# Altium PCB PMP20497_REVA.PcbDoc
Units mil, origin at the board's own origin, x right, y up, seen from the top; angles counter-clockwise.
Board outline 4000 x 2000 mil, 2 copper layers (Top Layer, Bottom Layer), stack 62 mil thick; 81 components, 31 nets, 187 pads, 65 vias.
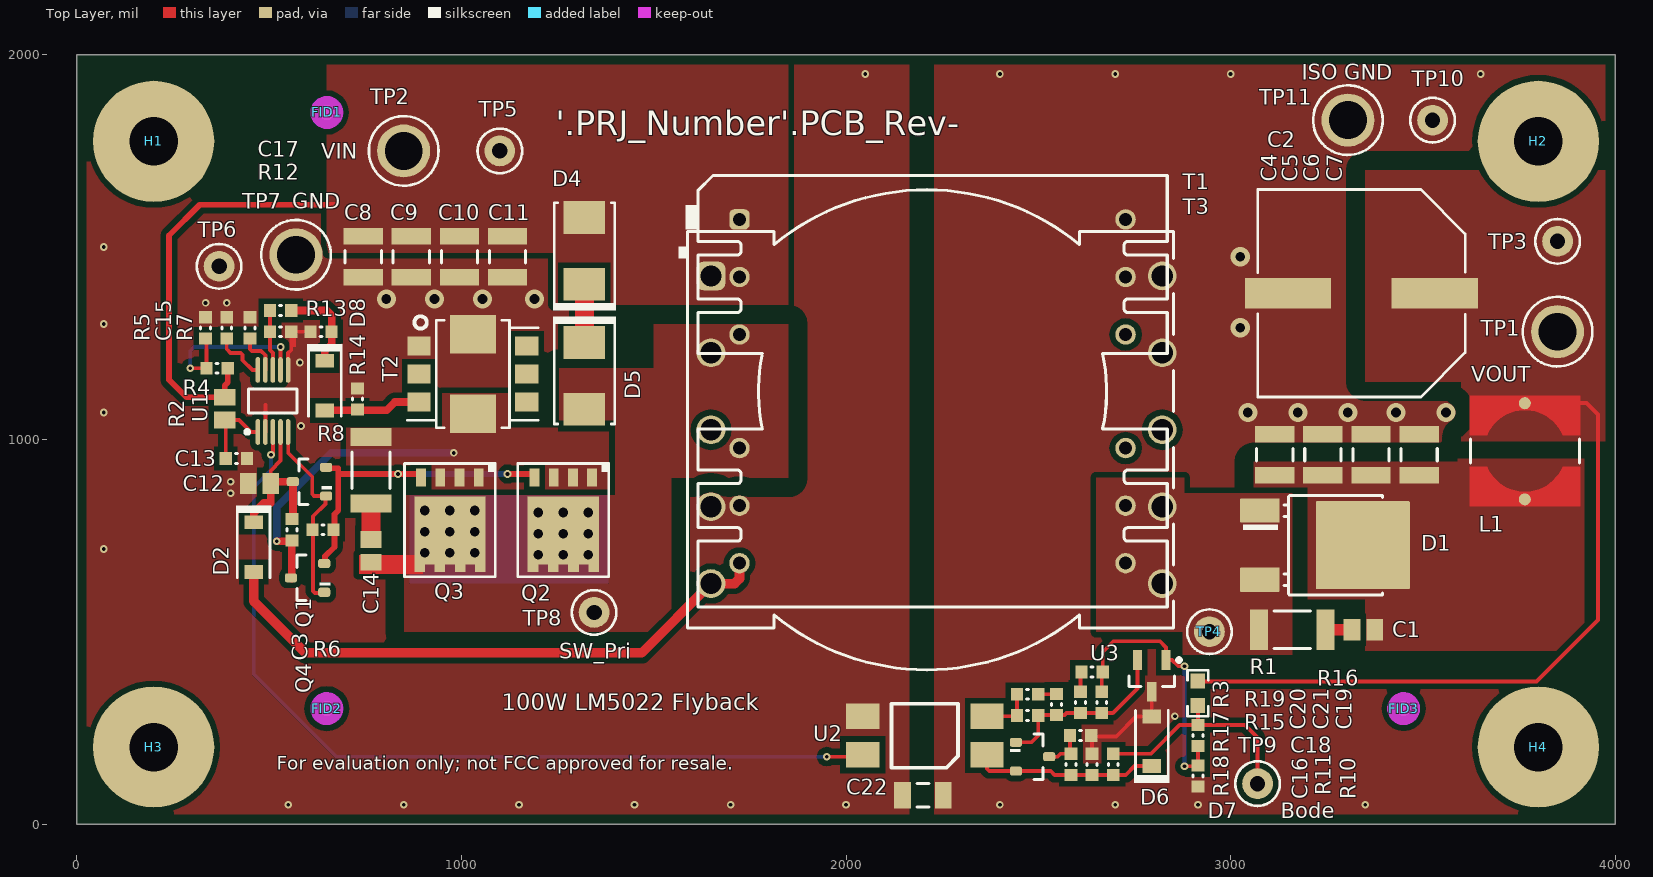
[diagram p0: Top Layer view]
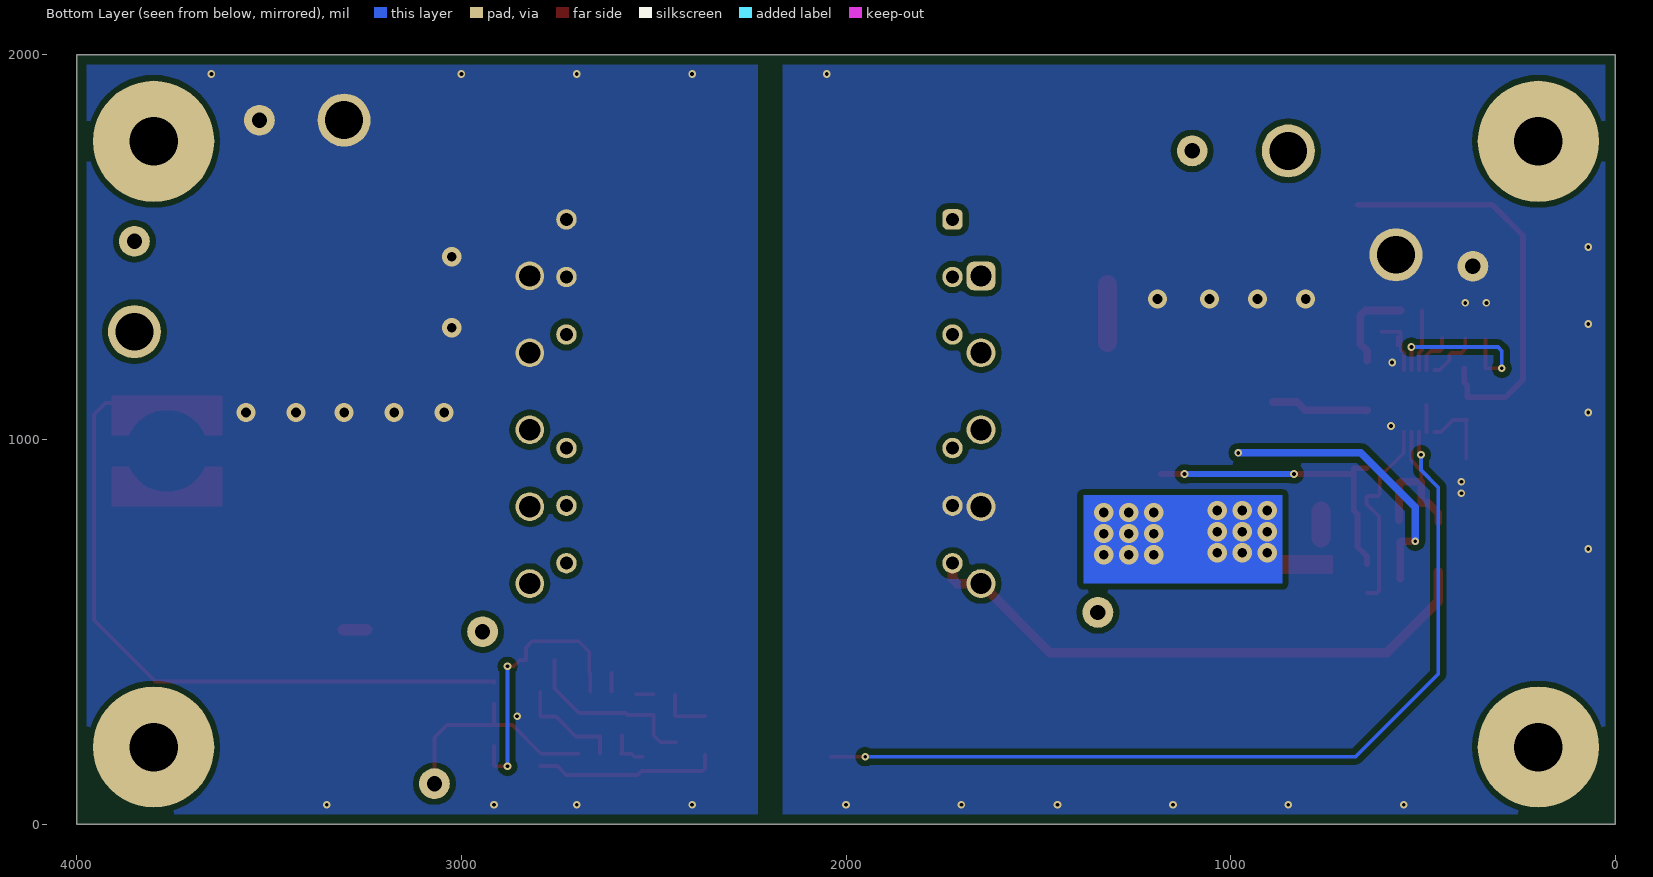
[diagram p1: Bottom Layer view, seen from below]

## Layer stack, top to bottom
Top Solder: solder mask 0.4, Solder Resist, Dk 3.5
Top Layer: signal copper 1.4
Dielectric1: core 59.2, FR-4, Dk 4.8
Bottom Layer: signal copper 1.4
Bottom Solder: solder mask 0.4, Solder Resist, Dk 3.5

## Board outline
0,0 4000,0 4000,2000 0,2000

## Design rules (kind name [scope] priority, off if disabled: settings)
AcuteAngle [All] p1: minimum=4.50000000000000E+0001 checktracksonly=FALSE
AssemblyTestPointUsage [All] p1: valid=2
BoardOutlineClearance BoardOutlineClearance_MountingHoles [OnCopper and InComponentClass('Mounting Holes')] p1: gap=40
BoardOutlineClearance BoardOutlineClearance_Poly [OnCopper and IsPoly] p2: gap=25
BoardOutlineClearance [OnCopper and Not InComponentClass('Logo') and not InComponentClass('FiducialMark') and not InRegion(1000,500,4000,800) and not InPoly] p3: gap=40
Clearance Clearance_NETC1 [(InPolygon AND InNet('netc1_1')) vs InNet('ISO GND')] p1: gap=50
Clearance Clearance_Vout_ISOGND [(InPolygon AND InNet('VOUT')) vs InNet('ISO GND')] p2: gap=50
Clearance Clearance_SWP_GND [(InPolygon AND InNet('SWP')) vs InNet('GND')] p3: gap=50
Clearance Clearance_Keepouts [((IsTrack Or IsArc) And Not InPoly) And IsFree and IsKeepOut vs ((IsTrack Or IsArc) And Not InPoly) And IsFree and IsKeepOut] p4: gap=0
Clearance Clearance_Poly [InPolygon] p5: gap=15
Clearance [All] p6: gap=7.87
ComponentClearance ComponentClearance_Inductor [(HasFootprint('Pulse_PA4621NL') OR HasFootprint ('Pulse_PA4826NL')) vs (HasFootprint('Pulse_PA4621NL') OR HasFootprint ('Pulse_PA4826NL'))] p1: gap=0 collisioncheckmode=3 verticalgap=0 showdistances=FALSE
ComponentClearance ComponentClearance_MountingHoles_FiducialMarks [InComponentClass('Mounting Holes') vs InComponentClass('FiducialMark')] p2: gap=50 collisioncheckmode=3 verticalgap=10 showdistances=FALSE
ComponentClearance ComponentClearance_Shunt [InComponentClass('Header') vs InComponentClass('Shunt')] p3: gap=0 collisioncheckmode=3 verticalgap=0 showdistances=FALSE
ComponentClearance ComponentClearance_Logo [InComponentClass('Logo')] p4: gap=50 collisioncheckmode=3 verticalgap=10 showdistances=FALSE
ComponentClearance ComponentClearance_ScrewToNut [(HasFootprint('NY PMS 440 0025 PH')) vs (HasFootprint('Keystone_1902C'))] p5: gap=5 collisioncheckmode=3 verticalgap=10 showdistances=FALSE
ComponentClearance ComponentClearance_MountingHoles [InComponentClass('Mounting Holes')] p6: gap=80 collisioncheckmode=3 verticalgap=100000 showdistances=FALSE
ComponentClearance ComponentClearance_SmallPassives [HasFootprint('0201*') or HasFootprint('0402*') or HasFootprint('0508') or HasFootprint('0603*') or HasFootprint('0612') or HasFootprint('0805*') or HasFootprint('0815*') or HasFootprint('0830*') or HasFootprint('1206*') or HasFootprint('1210*') or HasFootprint('1808*') or HasFootprint('1812*') or HasFootprint('1825*') or HasFootprint('2010*') or HasFootprint('2220*') or HasFootprint('2225*') or HasFootprint('2512*') or HasFootprint('2728*') or HasFootprint('3518*') vs HasFootprint('0201*') or HasFootprint('0402*') or HasFootprint('0508') or HasFootprint('0603*') or HasFootprint('0612') or HasFootprint('0805*') or HasFootprint('0815*') or HasFootprint('0830*') or HasFootprint('1206*') or HasFootprint('1210*') or HasFootprint('1808*') or HasFootprint('1812*') or HasFootprint('1825*') or HasFootprint('2010*') or HasFootprint('2220*') or HasFootprint('2225*') or HasFootprint('2512*') or HasFootprint('2728*') or HasFootprint('3518*')] p7: gap=14.96 collisioncheckmode=3 verticalgap=10 showdistances=FALSE
ComponentClearance ComponentClearance_THtoSMT [IsThruComponent vs IsSMTComponent] p8: gap=40 collisioncheckmode=3 verticalgap=30 showdistances=FALSE
ComponentClearance ComponentClearance_THtoTH [IsThruComponent vs IsThruComponent] p9: gap=30 collisioncheckmode=3 verticalgap=30 showdistances=FALSE
ComponentClearance [All] p10: gap=30 collisioncheckmode=3 verticalgap=10 showdistances=FALSE
DiffPairsRouting [All] p1: maxlimit=100 minlimit=10 mostfreqgap=10 toplayer_minwidth=15 toplayer_maxwidth=15 toplayer_prefwidth=15 bottomlayer_minwidth=15 bottomlayer_maxwidth=15 bottomlayer_prefwidth=15 maxuncoupledlength=1000
FabricationTestPointUsage TestPointUsage [All] p1: valid=2 allowmultiple=FALSE
FabricationTestpoint Testpoint [All] p1: side=3 testpointundercomponent=TRUE minsize=40 maxsize=100 preferedsize=60 minholesize=0 maxholesize=40 preferedholesize=32 testpointgrid=1 allowsidetop=TRUE allowsidebottom=TRUE usegrid=TRUE gridtolerance=0.01
FanoutControl Fanout_LCC [IsLCC] p1: bgadir=Out bgaviamode=Centered fanoutstyle=Auto fanoutdirection=Alternating viagrid=1 // Fanout_LCC (Default Rule)
FanoutControl Fanout_BGA [IsBGA] p2: bgadir=Out bgaviamode=Centered fanoutstyle=Auto fanoutdirection=Alternating viagrid=1 // Fanout_BGA (Default Rule)
FanoutControl Fanout_Default [All] p4: bgadir=Out bgaviamode=Centered fanoutstyle=Auto fanoutdirection=Alternating viagrid=1 // Fanout_Default (Default Rule)
FanoutControl Fanout_Small [(CompPinCount < 5)] p5: bgadir=Out bgaviamode=Centered fanoutstyle=Auto fanoutdirection=OutThenIn viagrid=1 // Fanout_Small (Default Rule)
Height [All] p1: minheight=0 maxheight=1200 prefheight=500
HoleSize [All] p1: absolutevalues=TRUE maxlimit=251 minlimit=7.87 maxpercent=80.000 minpercent=20.000
MinimumAnnularRing MinimumAnnularRing_ThermalPadVias [IsVia and InAnyComponent] p1: minimumring=5.91
MinimumAnnularRing [All] p2: minimumring=5
MinimumSolderMaskSliver MinimumSolderMaskSliver_Logo [InComponentClass('Logo') vs InComponentClass('Logo')] p1: minsoldermaskwidth=0.7
MinimumSolderMaskSliver [All] p2: minsoldermaskwidth=3.94
PlaneConnect [All] p1: planeconnectstyle=Direct reliefexpansion=10 reliefentries=4 reliefconductorwidth=10 reliefairgap=10
PolygonConnect [All] p1: connectstyle=Direct reliefconductorwidth=10 reliefentries=4 polygonreliefangle="90 Angle" airgapwidth=10
RoutingVias ThermalPadVias [IsVia and InAnyComponent] p1: holewidth=7.87 width=19.68 viastyle="Through Hole" minholewidth=7.87 minwidth=19.68 maxholewidth=12.99 maxwidth=23.62
RoutingVias [All] p2: holewidth=16 width=34 viastyle="Through Hole" minholewidth=7.87 minwidth=20 maxholewidth=40 maxwidth=65
SilkToBoardRegionClearance [Not ((IsComment or IsDesignator) And (Hide <> 'False')) and not InRegion(1000,500,4000,800)] p1:
SilkToSilkClearance SilkToSilkClearance_Pb-FreeLogo [(HasFootprint('Pb-Free_Overlay_Medium') OR HasFootprint('Pb-Free_Overlay_Small')) vs (HasFootprint('Pb-Free_Overlay_Medium') OR HasFootprint('Pb-Free_Overlay_Small'))] p1: silktosilkclearance=0
SilkToSilkClearance [All] p2: silktosilkclearance=4
SilkToSolderMaskClearance SilkToComponentPadClearance [(IsPad or IsFill or IsRegion) and InAnycomponent] p1: minsilkscreentomaskgap=5 clearancetoexposedcopper=TRUE
SilkToSolderMaskClearance "Silk to Solder Mask Opening" [All] p2: minsilkscreentomaskgap=4 clearancetoexposedcopper=FALSE
SolderMaskExpansion [All] p1: expansion=1.97
Width [All] p1: maxlimit=100 minlimit=6 preferedwidth=10 checkconnectedcopper=TRUE
14 further rules are at their usual default settings.

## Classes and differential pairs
component class AssemblyNote: ZZ1 ZZ2 ZZ3 ZZ4
component class FiducialMark: FID1 FID2 FID3
component class PMP20497_REVA_Hardware: FID1 FID2 FID3 H1 H2 H3 H4 Logo1 ZZ1 ZZ2 ZZ3 ZZ4
component class "Mounting Holes": H1 H2 H3 H4
component class PMP20497_REVA: C1 C2 C3 C4 C5 C6 C7 C8 C9 C10 C11 C12 C13 C14 C15 C16 C17 C18 C19 C20 C21 C22 D1 D2 D4 D5 D6 D7 D8 L1 Q1 Q2 Q3 Q4 R1 R2 R3 R4 R5 R6 R7 R8 R10 R11 R12 R13 R14 R15 R16 R17 R18 R19 T1 T2 T3 TP1 TP2 TP3 TP4 TP5 TP6 TP7 TP8 TP9 TP10 TP11 U1 U2 U3

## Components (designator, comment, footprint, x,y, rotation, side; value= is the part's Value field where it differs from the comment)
C1 "GRM2165C2A331JA01D" 0805L 3345,505 r180 top
C2 "EEV-FK1J151Q" SM_RADIAL_H13 3340,1380 r180 top
C3 "GRM188R71C104KA01D" 0603L 560,765 r270 top
C4 "GRM32ER71K475KE14L" 1210_270L 3115,960 r270 top
C5 "GRM32ER71K475KE14L" 1210_270L 3240,960 r270 top
C6 "GRM32ER71K475KE14L" 1210_270L 3365,960 r270 top
C7 "GRM32ER71K475KE14L" 1210_270L 3490,960 r270 top
C8 "GRM32ER71E226KE15L" 1210_270L 745,1475 r270 top
C9 "GRM32ER71E226KE15L" 1210_270L 870,1475 r270 top
C10 "GRM32ER71E226KE15L" 1210_270L 995,1475 r270 top
C11 "GRM32ER71E226KE15L" 1210_270L 1120,1475 r270 top
C12 "GRM21BR71C475KA73L" 0805L 475,885 r180 top
C13 "GRM188R71E105KA12D" 0603L 415,950 r0 top
C14 "GRM2165C2A681JA01D" 0805L 765,710 r90 top
C15 "GRM188R71C473KA01D" 0603L 390,1290 r90 top
C16 "GRM188R61C105KA93D" 0603L 2640,155 r90 top
C17 "GRM1885C1H101JA01D" 0603L 530,1280 r0 top
C18 "GRM188R71E105KA12D" 0603L 2610,230 r0 top
C19 "GRM188R71H332KA01D" 0603L 2665,316.3 r90 top
C20 "DNP" 0603L 2547.2,310.91 r90 top
C21 "GRM188R71E104KA01D" 0603L 2610,316.3 r270 top
C22 "GRM31BR73A102KW01L" 1206L 2200,75 r180 top
D1 "MBRD10200CT-13" DPAK 3210,725 r0 top
D2 "" SOD-123 460,720 r270 top
D4 "1SMB5944BT3G" SMB 1320,1490 r90 top
D5 "MBRS1100T3G" SMB 1320,1165 r270 top
D6 "MMSZ4699T1G" SOD-123 2795,215 r90 top
D7 "BAT54S-7-F" SOT-23L 2485,175 r0 top
D8 "1N4148W-7-F" SOD-123 645,1140 r270 top
FID1 "Fiducial" Fiducial10-20 650,1850 r0 top
FID2 "Fiducial" Fiducial10-20 650,300 r0 top
FID3 "Fiducial" Fiducial10-20 3450,300 r0 top
H1 "NY PMS 440 0025 PH" "NY PMS 440 0025 PH" 200,1775 r0 top locked
H2 "NY PMS 440 0025 PH" "NY PMS 440 0025 PH" 3800,1775 r0 top
H3 "NY PMS 440 0025 PH" "NY PMS 440 0025 PH" 200,200 r0 top locked
H4 "NY PMS 440 0025 PH" "NY PMS 440 0025 PH" 3800,200 r0 top locked
L1 "SRR6028-3R3Y" SRR6028 3765,970 r180 top
Logo1 "FCC disclaimer" FCC_disclaimer 2350,3380 r0 top
Q1 "FMMT618" SOT-23L 605,890 r180 top
Q2 "BSC093N15NS5ATMA1" PG-TDSON-8 1265,790 r270 top
Q3 "BSC093N15NS5ATMA1" PG-TDSON-8 970,790 r270 top
Q4 "FMMT718TA" SOT-23L 600,640 r180 top
R1 "CRCW20107R50JNEF" 2010L 3160,505 r180 top
R2 "CRCW08053R30JNEA" 0805L 385,1080 r90 top
R3 "CRCW060349R9FKEA" 0603 2915,340 r90 top
R4 "CRCW060366K5FKEA" 0603L 365,1185 r0 top
R5 "CRCW060310K0FKEA" 0603L 335,1290 r270 top
R6 "CRCW06034R70JNEA" 0603L 640,765 r0 top
R7 "CRCW0603174KFKEA" 0603L 450,1290 r270 top
R8 "CRCW20107R50JNEF" 2010L 765,920 r90 top
R10 "CRCW060310K0FKEA" 0603L 2695,155 r90 top
R11 "CRCW060347K0FKEA" 0603L 2585,155 r270 top
R12 "CRCW06033K24FKEA" 0603L 530,1335 r0 top
R13 "CRCW06031R50FKEA" 0603L 635,1280 r0 top
R14 "CRCW060310K0FKEA" 0603L 730,1105 r270 top
R15 "CRCW0603499RFKEA" 0603L 2472.2,282.2 r0 top
R16 "CRCW06034K99FKEA" 0603L 2640,395 r180 top
R17 "CRCW060347K0FKEA" 0603L 2915,230 r90 top
R18 "CRCW06031K10FKEA" 0603L 2915,125 r270 top
R19 "DNP" 0603L 2472.2,337.2 r0 top
T1 "PA4826NL" Pulse_PA4826NL 2210,1025 r0 top
T2 "PA1005.100NL" P82xx 1030,1170 r0 top
T3 "DNP" Pulse_PA4621NL 2225,1125 r0 top
TP1 "VOUT" Keystone1502-2 3850,1280 r0 top
TP2 "VIN" Keystone1502-2 850,1750 r0 top
TP3 "5000" Keystone5000 3850,1515 r0 top
TP4 "SW_Sec" Keystone5002 2945,500 r0 top
TP5 "5000" Keystone5000 1100,1750 r0 top
TP6 "5001" Keystone5001 370,1450 r0 top
TP7 "GND" Keystone1502-2 570,1480 r0 top
TP8 "SW_Pri" Keystone5002 1345,550 r0 top
TP9 "Bode" Keystone5002 3070,105 r0 top
TP10 "5001" Keystone5001 3525,1830 r0 top
TP11 "ISO GND" Keystone1502-2 3305,1830 r0 top
U1 "LM5022MME/NOPB" MUB10A_N 510,1100 r90 top
U2 "PS2501L-1-L-A" PS2501L 2205,230 r180 top
U3 "LMV431BIMFX/NOPB" MF03A_N 2795,385 r270 top
ZZ1 "This Assembly Note is for PCB labels only" AssemblyNoteLabel 185,3938 r0 top
ZZ2 "These assemblies are ESD sensitive, ESD precautions shall be observed." AssemblyNote 185,3829.11 r0 top
ZZ3 "These assemblies must be clean and free from flux and all contaminants. Use of no clean flux is not acceptable." AssemblyNote 185,3740.56 r0 top
ZZ4 "These assemblies must comply with workmanship standards IPC-A-610 Class 2, unless otherwise specified." AssemblyNote 185,3652 r0 top

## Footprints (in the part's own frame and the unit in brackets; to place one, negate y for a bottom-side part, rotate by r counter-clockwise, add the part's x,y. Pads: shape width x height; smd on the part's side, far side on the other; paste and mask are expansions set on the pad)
0603 [mm] "0603 from SM-752 data"
  rect 1x0.95 smd: 1(-0.8,0) 2(0.8,0)
  silkscreen extent -1.52,-0.69 1.52,0.69, body extent -0.87,-0.47 0.87,0.47, height 1
0603L [mm] "0603 from SM-752 data"
  rect 0.8x0.85 smd: 1(-0.7,0) 2(0.7,0)
  silkscreen extent -0.07,-0.33 0.07,0.33, body extent -0.87,-0.47 0.87,0.47, height 1
0805L [mm] "0805 from SM-752 data"
  rect 1.1x1.4 smd: 1(-0.75,0) 2(0.75,0)
  body extent -1.1,-0.72 1.1,0.72, height 1.45
1206L [mm] "1206 from SM-752 data"
  rect 1.1x1.75 smd: 1(-1.35,0) 2(1.35,0)
  silkscreen extent -0.4,-0.77 0.4,0.77, body extent -1.7,-0.9 1.7,0.9, height 1.35
1210_270L [mm] "1210"
  rect 1.1x2.6 smd: 1(-1.35,0) 2(1.35,0)
  silkscreen extent -0.4,-1.2 0.4,1.2, body extent -1.7,-1.35 1.7,1.35, height 2.7
2010L [mm]
  rect 1.2x2.7 smd: 1(-2.2,0) 2(2.2,0)
  silkscreen extent -1.2,-1.25 1.2,1.25, body extent -2.73,-1.45 2.73,1.45, height 1.66
AssemblyNote [mil] "Assembly Note"
AssemblyNoteLabel [mil] "Assembly Note for PCB Labels"
DPAK [mm] "D-PAK, 3-Pads, Body 6.22x6.73mm (max), TO-252AA using nominal STEP model"
  rrect6% 2.6x1.6 smd: 1(-3.4,2.28) 3(-3.4,-2.28)
  rrect2% 6.2x5.8 smd paste-2.9: 4(3.4,0)
  silkscreen extent -4.5,-3.3 4.7,3.28, body extent -3.86,-3.29 5.84,3.29, height 2.48
FCC_disclaimer [mil]
Fiducial10-20 [mm]
  round 1 smd mask+0.5: 1(0,0)
  Top Layer keep-out circle w1.178: c0,0 r0.5
Keystone1502-2 [mm] "Double Turret"
  round 3.5 hole 2.5: 1(0,0)
  silkscreen extent -2.3,-2.3 2.3,2.3, body extent -1.6,-1.6 1.59,1.6, height 5.62
Keystone5000 [mil] "For Keystone 500x miniature loop terminals"
  round 80 hole 40: 1(0,0)
  silkscreen extent -58,-58 58,58, body extent -49,-49 49,49, height 182
Keystone5001 [mil] "For Keystone 500x miniature loop terminals"
  round 80 hole 40: 1(0,0)
  silkscreen extent -58,-58 58,58, body extent -49,-49 49,49, height 182
Keystone5002 [mil] "For Keystone 500x miniature loop terminals"
  round 80 hole 40: 1(0,0)
  silkscreen extent -58,-58 58,58, body extent -49,-49 49,49, height 182
MF03A_N [mm] "SOT23, 3-Leads, Body 2.9x1.3mm, Pitch 0.95mm, Lead Span 2.4mm, IPC Medium Density"
  rect 1.3x0.6 smd: 1(-1.05,0.95) 2(-1.05,-0.95) 3(1.05,0)
  silkscreen extent -1.17,-1.5 0.7,1.93, body extent -0.7,-1.5 0.7,1.5, height 1.12
MUB10A_N [mm] "TSSOP, 10-Leads, Body 3x3mm, Pitch 0.5mm, IPC Medium Density"
  oval 1.7x0.3 smd: 1(-2.05,1) 2(-2.05,0.5) 3(-2.05,0) 4(-2.05,-0.5) 5(-2.05,-1) 6(2.05,-1) 7(2.05,-0.5) 8(2.05,0) 9(2.05,0.5) 10(2.05,1)
  silkscreen extent -2.17,-1.6 0.8,1.82, body extent -1.6,-1.6 1.6,1.6, height 1.09
"NY PMS 440 0025 PH" [mm] "4-40 nylon screw and mounting hole"
  round 8 hole 3.2: 1(0,0)
  body extent -3.3,-3.3 3.3,3.3, height 2.69
P82xx [mil] "Pulse recommended land pattern"
  rect 60x50 smd: 1(-140,73) 2(-140,0) 3(-140,-73) 4(140,-73) 5(140,0) 6(140,73)
  rect 120x100 smd: 7(0,-103) 8(0,103)
  silkscreen extent -170,-140 170,150, body extent -95,-140 95,140, height 215
PG-TDSON-8 [mm] "Infineon recommended land pattern"
  rect 1.2x0.65 smd: 1(-2.825,1.905) 2(-2.825,0.635) 3(-2.825,-0.635) 4(-2.825,-1.905)
  rect 0.5x0.7 smd: 5(3.175,-2) 6(3.175,-0.675) 7(3.175,0.675) 8(3.175,2)
  rect 4.5x4.7 smd paste-2.25: 9(0.675,0)
  silkscreen extent -3.74,-3 3.74,3, body extent -3.18,-2.89 3.18,2.9, height 1.1
PS2501L [mm] "NEC optocoupler"
  rect 2.2x1.7 smd: 1(-4.1,1.27) 2(-4.1,-1.27) 3(4.1,-1.27) 4(4.1,1.27)
  silkscreen extent -2.2,-2.1 2.2,2.12, body extent -5,-2.29 5,2.29, height 3.87
Pulse_PA4621NL [mm] "TH, 12-Leads, Body 31x28.5mm"
  rrect50% 1.35x1.35 hole 0.85: 1(-12.75,11.35)
  round 1.35 hole 0.85: 2(-12.75,7.55) 3(-12.75,3.75) 4(-12.75,-3.75) 5(-12.75,-7.55) 6(-12.75,-11.35) 7(12.75,-11.35) 8(12.75,-7.55) 9(12.75,-3.75) 10(12.75,3.75) 11(12.75,7.55) 12(12.75,11.35)
  silkscreen extent -16.3,-14.25 15.5,14.25, body extent -15.5,-14.25 15.5,14.25, height 28
Pulse_PA4826NL [mm] "TH, 10-Leads, Body 39.5x31.5mm"
  rrect50% 1.9x1.9 hole 1.4: 1(-14.25,10.16)
  round 1.9 hole 1.4: 2(-14.25,5.08) 3(-14.25,0) 4(-14.25,-5.08) 5(-14.25,-10.16) 6(15.55,-10.16) 7(15.55,-5.08) 8(15.55,0) 9(15.55,5.08) 10(15.55,10.16)
  silkscreen extent -16.4,-15.85 16.3,15.85, body extent -19.75,-15.75 19.75,15.75, height 20
SM_RADIAL_H13 [mm] "12.5 x 13.5mm:  Panasonic H13"
  rect 5.7x2 smd: 1(-4.85,0) 2(4.85,0)
  silkscreen extent -6.85,-6.85 6.85,6.85, body extent -6.85,-6.85 6.85,6.85, height 14
SMB [mil] "Molded Diode, 2-Leads, Body 5.4x3.6mm, IPC Medium Density, based on OnSemi component dimensions"
  rect 85x107.99 smd: 1(-87.01,0) 2(87.01,0)
  silkscreen extent -155,-82 125,82, body extent -106,-71 106,71, height 91
SOD-123 [mm] "On Semi recommended land pattern"
  rect 0.915x1.22 smd: 1(-1.637,0) 2(1.637,0)
  silkscreen extent -2.74,-1.17 2.03,1.17, body extent -1.93,-0.9 1.93,0.9, height 1.35
SOT-23L [mm] "SOT23, 3-Leads, Body 2.9x1.3mm, Pitch 0.95mm, Lead Span 2.5mm, IPC High Density"
  rrect50% 0.8x0.6 smd: 1(-1.1,0.95) 2(-1.1,-0.95) 3(1.1,0)
  silkscreen extent -1.5,-1.5 0.7,1.5, body extent -1.16,-1.45 1.21,1.45, height 1
SRR6028 [mm] "BOURNS"
  round 0.8 smd: 1(0,3.2) 2(0,-3.15)
  Top Layer region: 3.65,-1.05 3.65,-3.65 -3.65,-3.65 -3.65,-1.05 -2.487,-1.051 -1.745,-2.06 -0.627,-2.626 0.627,-2.626 1.745,-2.06 2.487,-1.051 2.487,-1.051
  Top Layer region: -3.65,1.05 -3.65,3.65 3.65,3.65 3.65,1.05 2.487,1.051 1.745,2.06 0.627,2.626 -0.627,2.626 -1.745,2.06 -2.487,1.051 -2.487,1.051
  silkscreen extent -3.6,-0.8 3.6,0.8

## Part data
C1: "CAP, CERM, 330 pF, 100 V, +/- 5%, C0G/NP0, 0805"
C2: "CAP, AL, 150uF, 63V, +/-20%, 0.16 ohm, SMD"
C3: "CAP, CERM, 0.1 µF, 16 V, +/- 10%, X7R, 0603"
C4 C5 C6 C7: "CAP, CERM, 4.7 µF, 80 V, +/- 10%, X7R, 1210"
C8 C9 C10 C11: "CAP, CERM, 22 µF, 25 V, +/- 10%, X7R, 1210"
C12: "CAP, CERM, 4.7 µF, 16 V, +/- 10%, X7R, 0805"
C13 C18: "CAP, CERM, 1 µF, 25 V, +/- 10%, X7R, 0603"
C14: "CAP, CERM, 680 pF, 100 V, +/- 5%, C0G/NP0, 0805"
C15: "CAP, CERM, 0.047 µF, 16 V, +/- 10%, X7R, 0603"
C16: "CAP, CERM, 1uF, 16V, +/-10%, X5R, 0603"
C17: "CAP, CERM, 100 pF, 50 V, +/- 5%, C0G/NP0, 0603"
C19: "CAP, CERM, 3300 pF, 50 V, +/- 10%, X7R, 0603"
C20: library part GRM188R71E473KA01D, "CAP, CERM, 0.047 µF, 25 V, +/- 10%, X7R, 0603"
C21: "CAP, CERM, 0.1 µF, 25 V, +/- 10%, X7R, 0603"
C22: "CAP, CERM, 1000 pF, 1000 V, +/- 10%, X7R, 1206"
D1: "Diode, Schottky, 200 V, 5 A, DPAK"
D2: library part 1N4148W-7-F, "Diode, Ultrafast, 100V, 0.15A, SOD-123"
D4: "Diode, Zener, 62 V, 550 mW, SMB"
D5: "Diode, Schottky, 100 V, 1 A, SMB"
D6: "Diode, Zener, 12 V, 500 mW, SOD-123"
D7: "Diode, Schottky, 30 V, 0.2 A, SOT-23"
D8: "Diode, Ultrafast, 100 V, 0.15 A, SOD-123"
FID1 FID2 FID3: "Fiducial mark.  There is nothing to buy or mount."
H1 H2 H3 H4: "Machine Screw, Round, #4-40 x 1/4, Nylon, Philips panhead"
L1: "Inductor, Drum Core, Ferrite, 3.3 µH, 2.5 A, 0.028 ohm, SMD"
Logo1: library part FCC_disclaimer, "FCC_disclaimer"
Q1: "Transistor, NPN, 20V, 1.5A, SOT-23"
Q2 Q3: "MOSFET, N-CH, 150 V, 87 A, PG-TDSON-8"
Q4: library part "FMMT718TA, Diodes Inc.", "Transistor, PNP, 20 V, 1.5 A, SOT-23"
R1 R8: "RES, 7.5, 5%, 0.75 W, AEC-Q200 Grade 0, 2010"
R2: "RES, 3.3, 5%, 0.125 W, 0805"
R3: "RES, 49.9, 1%, 0.1 W, 0603"
R4: "RES, 66.5 k, 1%, 0.1 W, 0603"
R5 R14: "RES, 10.0k ohm, 1%, 0.1W, 0603"
R6: "RES, 4.7, 5%, 0.1 W, 0603"
R7: "RES, 174 k, 1%, 0.1 W, 0603"
R10: "RES, 10.0 k, 1%, 0.1 W, 0603"
R11 R17: "RES, 47.0 k, 1%, 0.1 W, AEC-Q200 Grade 0, 0603"
R12: "RES, 3.24 k, 1%, 0.1 W, 0603"
R13: "RES, 1.50, 1%, 0.1 W, 0603"
R15: "RES, 499, 1%, 0.1 W, 0603"
R16: "RES, 4.99 k, 1%, 0.1 W, 0603"
R18: "RES, 1.10 k, 1%, 0.1 W, 0603"
R19: library part CRCW06031K10FKEA, "RES, 1.10 k, 1%, 0.1 W, 0603"
T1: "Transformer, 8.3 uH, TH"
T2: "SMT Current Sense Tranformer"
T3: library part PA4621NL, "Transformer, 10 uH, TH"
TP1 TP2 TP7 TP11: library part 1502-2, "Terminal, Turret, TH, Double"
TP3 TP5: "Test Point, TH, Miniature, Red"
TP4 TP8 TP9: library part 5002, "Test Point, TH, Miniature, White"
TP6 TP10: "Test Point, TH, Miniature, Black"
U1: "60V Low Side Controller for Boost and SEPIC, 10-pin MSOP, Pb-Free"
U2: "High Isolation Voltage Single Transistor Type OptoCoupler 200-400% CTR"
U3: "Low-Voltage (1.24V) Adjustable Precision Shunt Regulators, 3-pin SOT-23, Pb-Free"
ZZ1: library part AssemblyNoteLabel
ZZ2 ZZ3 ZZ4: library part AssemblyNote

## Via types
v1: diameter 20, hole 10, Top Layer to Bottom Layer, 36 vias
v2: diameter 50, hole 25, Top Layer to Bottom Layer, 29 vias

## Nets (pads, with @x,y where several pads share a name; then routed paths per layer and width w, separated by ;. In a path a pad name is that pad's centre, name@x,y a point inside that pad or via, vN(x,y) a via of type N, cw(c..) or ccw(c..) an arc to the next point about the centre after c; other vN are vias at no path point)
AUX: D2.2 T1.5 T3.6 | length 1514.4
  Top Layer w25: D2.2@460,655.22 460,579.69 594.69,445 1468.98,445 T1.5 1710,625 1723.03,638.03 T3.6
COMP: U1.3 U2.4 | length 2317.6
  Top Layer w10: v1(505,960) 510,965 U1.3 ; v1(1950,175) U2.4@2038.58,175
  Bottom Layer w10: v1(505,960) 505,920 460,875 460,390 675,175 v1(1950,175)
CS: C17.1 R12.1 U1.8 | length 157.4
  Top Layer w10: R12.1 C17.1 502.44,1232.56 510,1225 U1.8
GND: C8.2 C9.2 C10.2 C11.2 C12.2 C13.2 C15.2 C17.2 C22.2 R5.1 R7.1 R13.1 R14.1 T1.4 T2.1 T2.8 T3.5 TP6.1 TP7.1 U1.2 U1.6 U2.3 | length 223
  Top Layer w10: U1.2 490.31,1089.69 ; U1.6 549.37,1224.37 557.56,1232.56 C17.2 R13.1
  other v1: 550,50 850,50 1150,50 1450,50 1700,50 2000,50 70,715 400,860 400,890 582.83,1035 70,1070 580,1200 70,1300 335,1355 390,1355 70,1500 2050,1950
  other v2: 805,1365 930,1365 1055,1365 1190,1365
"ISO GND": C2.2 C4.1 C5.1 C6.1 C7.1 C16.2 C18.2 C22.1 D6.2 R18.2 T1.9 T1.10 T3.11 T3.12 TP10.1 TP11.1 U3.3 | length 285.7
  Top Layer w10: C16.2 2640,227.56 2702.56,227.56 2754.47,279.47 D6.2 U3.3
  other v1: 2400,50 2700,50 2915,50 3350,50 2855,280 2400,1950 2700,1950 3000,1950 3650,1950
  other v2: 3045,1070 3175,1070 3305,1070 3430,1070 3560,1070 3025,1290 3025,1475
NetC1_1: C1.1 C4.2 C5.2 C6.2 C7.2 D1.4 L1.1
NetC1_2: C1.2 R1.1 | length 60.8
  Top Layer w30: R1.1 C1.2@3307.44,505
NetC3_2: C3.2 Q2.1 Q2.2 Q2.3 Q3.1 Q3.2 Q3.3 Q4.3 R8.2 T2.7 | length 738.9
  Top Layer w20: v1(520,735) C3.2@557.56,735 ; Q4.3@558.9,637.8 C3.2@558.9,731.93
  Bottom Layer w20: v1(520,735) 520,823.68 661.32,965 v1(980,965)
NetC14_2: C14.2 R8.1 | length 68.9
  Top Layer w50: C14.2@765,744.45 R8.1@765,813.31
NetC16_1: C16.1 D6.1 D7.2 R10.1 R11.2 U2.1 | length 481.3
  Top Layer w10: U2.1 2366.42,143.58 2372.4,137.6 D7.2 2532.4,137.6 2542.56,127.44 C16.1 R10.1 2727.44,127.44 2750.53,150.53 D6.1
NetC18_1: C18.1 D7.3 R11.1 | length 108.3
  Top Layer w10: D7.3 2550,175 2557.56,182.56 R11.1 2582.44,185.12 C18.1
NetC19_1: C19.1 C20.1 C21.2 D7.1 R15.2 U3.2 | length 478.4
  Top Layer w10: D7.1 2482.4,212.4 2499.76,229.76 R15.2 2500.9,283.35 C20.1 2568.35,283.35 2573.74,288.74 C19.1 2693.74,288.74 2757.6,352.6 U3.2
NetC19_2: C19.2 R16.1 R17.1 R18.1 U3.1 | length 717.2
  Top Layer w10: C19.2 R16.1@2665,392.44 ; R16.1 2667.56,447.56 2695,475 2816.77,475 2832.4,459.37 U3.1 2847.56,426.34 2863.9,410 v1(2880,410) ; v1(2880,150) 2912.44,150 R18.1 R17.1
  Bottom Layer w10: v1(2880,150) v1(2880,410)
NetC20_2: C20.2 R19.2 | length 46.2
  Top Layer w10: R19.2 C20.2@2545.94,337.2
NetC21_1: C21.1 R16.2 | length 48.7
  Top Layer w10: C21.1 R16.2@2610,392.56
NetD4_1: D4.1 D5.1 | length 151
  Top Layer w50: D5.1 D4.1
NetD8_1: D8.1 R12.2 R13.2 | length 235.4
  Top Layer w20: R12.2 650,1335 662.56,1322.44 R13.2 662.56,1247.56 645,1230 D8.1
NetD8_2: D8.2 R14.2 T2.3 | length 254.6
  Top Layer w20: D8.2@645.53,1075 D8.2 805.53,1075.53 827,1097 T2.3
NetQ1_2: Q1.2 Q2.4 Q3.4 Q4.2 R6.2 | length 850.1
  Top Layer w15: Q4.2@645.51,675.2 645.51,696.11 669.76,720.36 669.76,805.36 679.8,815.4 679.8,910 ; Q1.2@646.5,925.2 679.8,925.2 679.8,910 ; Q3.4@886.22,910 v1(835,910) 679.8,910 ; v1(1120,910) Q2.4@1181.22,910
  Bottom Layer w15: v1(835,910) v1(1120,910)
NetR3_1: R3.1 R10.2 R17.2 TP9.1 | length 594.4
  Top Layer w10: R10.2 2792.56,182.56 2867.56,257.56 R17.2 ; R3.1@2915,312.44 R17.2 ; TP9.1 3070,225 3037.44,257.56 R17.2
NetR15_1: R15.1 R19.1 U2.2 | length 134.1
  Top Layer w10: U2.2 2442.44,280 R15.1 R19.1
OUT: Q1.1 Q4.1 R6.1 U1.5 | length 516
  Top Layer w10: U1.5 550,1018.66 550,965 612.2,902.8 612.2,857.8 617.2,852.8 644.09,852.8 646.5,850.4 646.5,832.09 614.65,800.24 614.65,605.36 619.61,600.4 Q4.1@645.51,600.4
RT: R7.2 U1.9 | length 112.5
  Top Layer w10: R7.2 450,1235 455,1230 479.02,1230 490.31,1218.7 U1.9
SS: C15.1 U1.10 | length 138.9
  Top Layer w10: C15.1 390,1235 400,1225 426.34,1225 431.34,1220 431.34,1205.83 456.46,1180.71 U1.10
SWP: C14.1 D5.2 Q2.5 Q2.6 Q2.7 Q2.8 Q2.9 Q3.5 Q3.6 Q3.7 Q3.8 Q3.9 T1.2 T3.3 T3.4 TP8.1
  other v2: 1200,700 1265,700 1330,700 905,705 970,705 1035,705 1200,755 1265,755 1330,755 905,760 970,760 1035,760 1200,810 1265,810 1330,810 905,815 970,815 1035,815
SWS: D1.1 D1.3 R1.2 T1.6 T1.7 T3.7 T3.8 TP4.1
UVLO: R4.1 R5.2 U1.7 | length 460.6
  Top Layer w10: v1(295,1185) R4.1 R5.2@337.44,1260 ; U1.7 v1@529.68,1239.68
  Bottom Layer w10: v1(295,1185) 295,1230 305,1240 v1(530,1240)
VCC: C3.1 C12.1 D2.1 Q1.3 U1.4 | length 425.8
  Top Layer w10: C12.1 504.53,890 504.53,919.53 529.68,944.68 U1.4 ; Q1.3@559.88,887.8 Q1.3@562.2,885.48
  Top Layer w20: D2.1 460,808 486.53,834.53 504.53,834.53 C12.1 ; C12.1@504.53,890 Q1.3@557.68,890 ; C3.1@562.2,790.36 Q1.3@562.2,885.48
VIN: C8.1 C9.1 C10.1 C11.1 D4.2 R2.2 R4.2 T1.1 T3.1 T3.2 TP2.1 TP5.1 | length 1080.6
  Top Layer w15: R4.2 392.56,1147.56 385,1140 R2.2 285.47,1109.53 240,1155 240,1530 320,1610 670,1610
"VIN U1": C13.1 R2.1 U1.1 | length 196.6
  Top Layer w10: R2.1 421.69,1050.47 452.87,1019.29 U1.1 ; C13.1 R2.1@387.44,1048.03
VOUT: C2.1 L1.2 R3.2 TP1.1 TP3.1 | length 1726.3
  Top Layer w10: R3.2@2915,367.56 2915,370.35 3795.35,370.35 3955,530 3955,1065 3925,1095 3885,1095
pads on no net: FID1.1 FID2.1 FID3.1 H1.1 H2.1 H3.1 H4.1 T1.3 T1.8 T2.2 T2.4 T2.5 T2.6 T3.9 T3.10

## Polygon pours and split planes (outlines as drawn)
VIN on Top Layer "Vin" (solid, remove dead copper, pour order 0): 650,2000 650,1485 1240,1485 1240,1350 1850,1350 1850,2000
SWS on Top Layer "SWS" (solid, remove dead copper, pour order 10): 2650,900 2650,500 2875,500 2875,440 3160,440 3160,860 2880,860 2880,900
NetC1_1 on Top Layer "C1" (solid, remove dead copper, pour order 12): 3059.88,950 3059.88,875 3200,875 3200,585 3350,585 3350,450 3920,450 3920,850 3920,950 3585,950 3580,950
VOUT on Top Layer "Vout" (solid, remove dead copper, pour order 14): 3350,1700 3350,1150 3600,1150 3600,995 4000,995 4000,1700
GND on Top Layer "GND" (solid, remove dead copper, pour order 16): 0,2000 0,0 2160,0 2165,-5 2165,2000
"ISO GND" on Top Layer "ISO GND" (solid, remove dead copper, pour order 18): 2230,2000 2230,0 4000,0 4000,2000
SWP on Top Layer "SWP" (solid, remove dead copper, pour order 6): 851.89,855 851.89,642.76 851.89,636.65 851.89,500 1545,500 1545,900 1850,900 1850,1300 1500,1300 1500,1184.68 1255,1184.68 1255,1050 1400,1050 1400,855
NetC3_2 on Top Layer "Q2" (solid, remove dead copper, pour order 8): 950,1120 950,1030 700,1030 700,870 1383.11,870 1383.11,1030 1120,1030 1120,1120
GND on Bottom Layer "GND" (solid, remove dead copper, pour order 20): 0,1990 0,-10 2160,-10 2165,-15 2165,1990
"ISO GND" on Bottom Layer "ISO GND" (solid, remove dead copper, pour order 22): 2230,1974.51 2230,-25.49 4000,-25.49 4000,1974.51

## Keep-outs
Keep-Out Layer:
  text ".Layer_Name" at 577,-858.49 h60

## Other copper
Top Layer:
  rectangle net GND: 557.56,1240 570,1270
  rectangle net SWP: 733.5,650 900,700
  text ".Layer_Name" at 577,-858.49 h60
Bottom Layer:
  rectangle net SWP: 865,625 1383.11,855
  text ".Layer_Name" at 577,-858.49 h60

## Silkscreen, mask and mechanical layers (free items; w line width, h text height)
Top Overlay:
  text "'.PRJ_Number'.PCB_Rev-" at 1245,1770 h108.27
  text "100W LM5022 Flyback" at 1105,281.28 h72.83
  text ".Layer_Name" at 577,-858.49 h60
Bottom Overlay:
  text ".Layer_Name" at 577,-858.49 h60
Top Paste:
  text ".Layer_Name" at 577,-858.49 h60
Bottom Paste:
  text ".Layer_Name" at 577,-858.49 h60
Top Solder:
  text ".Layer_Name" at 577,-858.49 h60
  text ".Layer_Name" at 577,-858.49 h60
Bottom Solder:
  text ".Layer_Name" at 577,-858.49 h60
Drill Guide:
  text ".Layer_Name" at 577,-858.49 h60
M1 Board Outline:
  the board outline again, w10
  text ".Layer_Name" at 577,-858.49 h60
M2 Board Dimensions:
  rectangle: 125,-400 500,-275
  rectangle: 0,-275 125,-150
  lines w7: 0,-275 1000,-275 ; 125,-400 125,-150 ; 250,-400 250,-150 ; 500,-400 500,-150 ; 750,-400 750,-150 ; 0,-400 0,-150 1000,-150 1000,-400 0,-400
  text ".Layer_Name" at 577,-858.49 h60
M3 3D STEP Top:
  text ".Layer_Name" at 577,-858.49 h60
M4 3D STEP Bottom:
  text ".Layer_Name" at 577,-858.49 h60
M5 Assembly Top:
  lines w10: -292,-930.17 6308,-930.17 ; -292,-726.83 6310,-726.83 ; -292,-523.5 -292,-1133.5 3713,-1133.5 6310,-1133.5 6310,-523.5 -291.5,-523.5 -291.5,-1133.5 1284,-1133.5 ; 2173,-1133.5 2173,-523.5 ; 3440,-726.83 3440,-523.5 ; 4280,-726.83 4280,-523.5 ; 4902,-1140 4902,-937.17
  text "COMPONENTS MARKED 'DNP' SHOULD NOT BE POPULATED." at 1153.5,-318.5 h60
  text "ASSEMBLY VARIANT:" at 1153,-434 h60
  text ".VariantName" at 2189,-434 h60
  text "PCB VIEWED FROM TOP SIDE" at -228.5,-655.67 h60
  text "BOARD #:" at 2248,-655.67 h60
  text ".PRJ_Number" at 2793.5,-655.67 h60
  text "REV:" at 3638,-655.67 h60
  text ".PCB_Rev" at 3929.5,-655.67 h60
  text "SVN REV:" at 4476,-655.67 h60
  text ".VersionControl_RevNumber" at 4982,-655.67 h60
  text "TID #:" at 2248,-859 h60
  text ".TID" at 2793.5,-859 h60
  text "PLOT NAME =" at -228.5,-1064.34 h60
  text ".plot_File_Name" at 577,-1064.34 h60
  text "GENERATED    :" at 2250,-1064.34 h60
  text ".Print_Date" at 3119.5,-1064.34 h60
  text ".Print_Time" at 3848.5,-1064.34 h60
  text "TEXAS INSTRUMENTS" at 5113,-1064.34 h60
M6 Assembly Bottom:
  lines w10: -292.5,-727.33 6309.5,-727.33 ; -290.5,-930.67 6309.5,-930.67 ; 1115.5,-1140.5 1115.5,-937.67 ; 1737.5,-727.33 1737.5,-524 ; 2577.5,-727.33 2577.5,-524 ; 3844.5,-1134 3844.5,-524 ; 4733.5,-1134 6309,-1134 6309,-524 -292.5,-524 -292.5,-1134 2304.5,-1134 6309.5,-1134 6309.5,-524
  text "COMPONENTS MARKED 'DNP' SHOULD NOT BE POPULATED." at 6102,-318 h60
  text ".VariantName" at 5058,-434 h60
  text "ASSEMBLY VARIANT:" at 6097,-434 h60
  text ".VersionControl_RevNumber" at 1035.5,-656.17 h60
  text "SVN REV:" at 1541.5,-656.17 h60
  text ".PCB_Rev" at 2088,-656.17 h60
  text "REV:" at 2379.5,-656.17 h60
  text ".PRJ_Number" at 3224,-656.17 h60
  text "BOARD #:" at 3769.5,-656.17 h60
  text "PCB VIEWED FROM BOTTOM SIDE" at 6246,-656.17 h60
  text ".TID" at 3224,-859.5 h60
  text "TID #:" at 3769.5,-859.5 h60
  text "TEXAS INSTRUMENTS" at 904.5,-1064.84 h60
  text ".Print_Time" at 2169,-1064.84 h60
  text ".Print_Date" at 2898,-1064.84 h60
  text "GENERATED    :" at 3767.5,-1064.84 h60
  text ".plot_File_Name" at 5440.5,-1064.84 h60
  text "PLOT NAME =" at 6246,-1064.84 h60
M9 Title Sheet:
  drawing of 57 lines, arcs and shapes, not listed
  text "1" at 739.84,8036.5 h70
  text "2" at 3235.5,8036.5 h70
  text "3" at 5724.84,8036.5 h70
  text "4" at 8231.51,8036.5 h70
  text "5" at 10730.5,8036.5 h70
  text "6" at 13235.5,8036.5 h70
  text "A" at -416.5,6893.5 h70
  text "A" at 14383.5,6893.5 h70
  text "B" at -416.5,4513.5 h70
  text "B" at 14383.5,4513.5 h70
  text "C" at -416.5,2138.5 h70
  text "C" at 14383.5,2138.5 h70
  text "PROJECT TITLE:" at 11343.5,277.5 h45
  text ".PRJ_Title" at 11393.5,144.17 h70
  text "DESIGNED FOR:" at 11343.5,-23.5 h45
  text ".PRJ_Customer" at 11393.5,-163.5 h70
  text "D" at -416.5,-231.5 h70
  text "D" at 14383.5,-231.5 h70
  text "FILE NAME:" at 11343.5,-323.5 h45
  text ".PCB_File_Name_No_Path" at 11393.5,-443.5 h70
  text "Texas Instruments (TI) and/or its licensors do not warrant the accuracy or completeness of this specification" at 6374,-605.34 h45
  text "ENGINEER:" at 11343.5,-613.5 h45
  text "LAYOUT BY:" at 12848.5,-613.5 h45
  text "or any information contained therein. TI and/or its licensors do not warrant that this design will meet" at 6329.01,-718 h45
  text ".PRJ_Engineer" at 11393.5,-768.49 h70
  text ".PCB_Layout" at 12899,-768.49 h70
  text "the specifications, will be suitable for your application or fit for any particular purpose, or will operate in" at 6329.01,-830.67 h45
  text ".Layer_Name" at 577,-858.49 h60
  text "ALTIUM DESIGNER VERSION:" at 12848.5,-923.5 h45
  text "an implementation. TI and/or its licensors do not warrant that the design is production worthy. You should" at 6329.01,-943.33 h45
  text "completely validate and test your design implementation to confirm the system functionality for your application." at 6374,-1056 h45
  text ".print_Scale" at 11393.5,-1056.83 h70
  text ".Application_BuildNumber" at 12899,-1056.83 h70
  text "1" at 739.84,-1263.5 h70
  text "2" at 3235.5,-1263.5 h70
  text "3" at 5724.84,-1263.5 h70
  text "4" at 8231.51,-1263.5 h70
  text "5" at 10730.5,-1263.5 h70
  text "6" at 13235.5,-1263.5 h70
M10 Fab Notes:
  drawing of 173 lines, arcs and shapes, not listed
  text "DESIGN INFORMATION" at 12378.02,6201 h60
  text "MIN. TRACK WIDTH:" at 11733.46,6021 h60
  text "8" at 12829.7,6021 h60
  text "MIL" at 12984.46,6021 h60
  text "MIN. CLEARANCE:" at 11733.46,5889 h60
  text "0.2" at 12769.7,5889 h60
  text "mm" at 12984.46,5889 h60
  text "MIN. VIA PAD SIZE:" at 11733.46,5757 h60
  text "20" at 12799.71,5757 h60
  text "MIL" at 12984.46,5757 h60
  text "0.127mm (5MIL)" at 12428.46,5615.29 h60
  text "MINIMUM ANNULAR RING" at 11404.23,5611 h60
  text "EXTERNAL" at 13136.46,5611 h60
  text "PER" at 11604.23,5493 h60
  text "IPC-D-275 CLASS 2 LEVEL C" at 11824.23,5493 h60
  text "MIL, HOLES" at 13312.46,5380.71 h60
  text "+/-" at 12920,5380 h60
  text "+/-" at 13774,5380 h60
  text "REGISTRATION TOLERANCES:" at 11404.23,5375 h60
  text "METAL" at 12604,5375 h60
  text "5" at 13180.2,5375 h60
  text "3" at 14013.2,5375 h60
  text "MIL" at 14129.46,5375 h60
  text "+/-" at 13774,5262 h60
  text "HOLE SIZE TOLERANCE (UNLESS OTHERWISE SPECIFIED):" at 11404.23,5257 h60
  text "3" at 14013.2,5257 h60
  text "MIL" at 14129.46,5257 h60
  text "MATERIAL:" at 11329.46,5047.54 h60
  text "FR-4 High Tg" at 12315.9,4907.21 h60
  text "FR-408" at 11750.46,4898.64 h60
  text "OTHER" at 13238.46,4898.64 h60
  text "X" at 12161,4895 h60
  text "62 MIL (1.6mm) +/-10%" at 12070.56,4735.92 h60
  text "THICKNESS:" at 11404.23,4731.64 h60
  text "X" at 11942.4,4731.64 h60
  text "OTHER" at 13355.46,4731.64 h60
  text "TOLERANCE:" at 11404.23,4573.64 h60
  text "X" at 12243.53,4573.64 h60
  text "ANSI IPC-6012 TYPE 3 CLASS 2" at 12430.48,4573.64 h60
  text "OTHER +/-" at 12430.46,4417.64 h60
  text "BOW & TWIST:" at 11404.23,4260.64 h60
  text "X" at 12243.53,4260.64 h60
  text "ANSI IPC-6012 TYPE 3 CLASS 2" at 12430.48,4260.64 h60
  text "OTHER +/-" at 12430.46,4102.13 h60
  text "DRILLING:" at 11329.46,3963.64 h60
  text "REFERENCE:" at 11404.23,3846.64 h60
  text "X" at 12052.46,3846.64 h60
  text "AS SHOWN" at 12239.46,3846.64 h60
  text "X" at 12953.46,3846.64 h60
  text "NC_DRILL FILES" at 13090.46,3846.64 h60
  text "PTH COPPER THICKNESS:" at 11404.23,3688.64 h60
  text "X" at 12534.46,3688.64 h60
  text "20-30 um" at 12671.46,3688.64 h60
  text "OTHER" at 13388.46,3688.64 h60
  text "BOARD FINISH:" at 11329.46,3529.64 h60
  text "SILKSCREEN:" at 11484.68,3411.64 h60
  text "X" at 12433.46,3411.64 h60
  text "TOP" at 12559.46,3411.64 h60
  text "X" at 12943.46,3411.64 h60
  text "BOTTOM" at 13070.46,3411.64 h60
  text "SILKSCREEN COLOR:" at 11484.68,3244.64 h60
  text "X" at 12432.42,3244.64 h60
  text "WHITE" at 12559.46,3244.64 h60
  text "OTHER" at 13070.46,3244.64 h60
  text "X" at 12563.42,3085.44 h60
  text "GREEN" at 12690.46,3085.44 h60
  text "OTHER" at 13308.46,3085.44 h60
  text "SOLDER RESIST COLOR:" at 11484.68,3074.64 h60
  text "X" at 12563.42,2915.44 h60
  text "MATTE" at 12690.46,2915.44 h60
  text "SEMI-GLOSS" at 13308,2914.8 h60
  text "IMMERSION GOLD (ENIG)" at 12390.46,2726.92 h60
  text "ENEPIG" at 13728,2723.64 h60
  text "SURFACE FINISH:" at 11329.46,2722.64 h60
  text "X" at 12203.51,2722.64 h60
  text "IMM. TIN/SILVER OR EQUIV" at 11659,2565.64 h60
  text "OTHER" at 13090.46,2565.64 h60
  text "ARRAY/PANEL:" at 11329.46,2386.64 h60
  text "CUT AND TRIM PER M1 BOARD OUTLINE" at 12390.46,2382.35 h60
  text "X" at 12200,2380 h60
  text "N.C. ROUTE" at 12390.46,2230.64 h60
  text "V. SCORE" at 13256.46,2230.64 h60
  text "CERTIFICATION:" at 11329.46,2093.64 h60
  text "MATERIALS AND WORKMANSHIP FOR ALL PCBS" at 12054.46,2093.64 h60
  text "TO MEET OR EXCEED THE REQUIREMENTS OF:" at 12054.46,1995.64 h60
  text "X" at 11680.96,1859.13 h60
  text "ANSI IPC-A-600F CLASS ->" at 11819.96,1859.13 h60
  text "X" at 13459.02,1859.13 h60
  text "2" at 13577.96,1859.14 h60
  text "1" at 13262.96,1857.64 h60
  text "3" at 13931.96,1857.64 h60
  text "X" at 12495.02,1699.64 h60
  text "RoHS" at 12631.96,1699.64 h60
  text "OTHER" at 13276.36,1699.64 h60
  text "PER ORDER" at 13673.42,1699.64 h60
  text "ALL BOARDS MUST MEET OR EXCEED UL94-V0 REQUIREMENTS." at 11357,1534 h60
  text "PCB MUST BEAR THE UL94V-0 UL REGISTERED MATERIAL ID NUMBER" at 11357,1414 h60
  text "ADDITIONAL REQUIREMENTS:" at 11329.46,1240.64 h60
  text "MICROSECTION:" at 11404.23,1125.64 h60
  text "YES" at 12309.96,1125.64 h60
  text "REQUIRED" at 13171.46,969.49 h60
  text "BARE BOARD ELEC. TEST:" at 11404.23,966.64 h60
  text "NONE" at 12709.96,966.64 h60
  text "X" at 13044.46,966.64 h60
  text "PER ORDER" at 13763.46,966.64 h60
  text ".Layer_Name" at 577,-858.49 h60
M11 Gerber Information:
  lines w10: -292,-930.17 6308,-930.17 ; -292,-726.83 6310,-726.83 ; -292,-523.5 -292,-1133.5 3713,-1133.5 6310,-1133.5 6310,-523.5 -291.5,-523.5 -291.5,-1133.5 1284,-1133.5 ; 2173,-1133.5 2173,-523.5 ; 3440,-726.83 3440,-523.5 ; 4280,-726.83 4280,-523.5 ; 4902,-1140 4902,-937.17
  text "ALL ARTWORK VIEWED FROM TOP SIDE" at -228.5,-655.67 h60
  text "BOARD #:" at 2248,-655.67 h60
  text ".PRJ_Number" at 2793.5,-655.67 h60
  text "REV:" at 3638,-655.67 h60
  text ".PCB_Rev" at 3929.5,-655.67 h60
  text "SVN REV:" at 4476,-655.67 h60
  text ".VersionControl_RevNumber" at 4982,-655.67 h60
  text "LAYER NAME =" at -228.5,-858.49 h60
  text "TID #:" at 2248,-859 h60
  text ".TID" at 2793.5,-859 h60
  text "PLOT NAME =" at -228.5,-1064.34 h60
  text ".plot_File_Name" at 577,-1064.34 h60
  text "GENERATED    :" at 2250,-1064.34 h60
  text ".Print_Date" at 3119.5,-1064.34 h60
  text ".Print_Time" at 3848.5,-1064.34 h60
  text "TEXAS INSTRUMENTS" at 5113,-1064.34 h60
M12 Stackup:
  drawing of 191 lines, arcs and shapes, not listed
  text "Layer" at 9790.34,7830 h60
  text "Name" at 10200.26,7830 h60
  text "Material" at 11130,7830 h60
  text "Thickness" at 11989.77,7830 h60
  text "Constant" at 12639.6,7830 h60
  text "Board Layer Stack" at 13209.46,7830 h60
  text "1" at 9790.34,7710 h60
  text "Top Overlay" at 10200.26,7710 h60
  text "2" at 9790.34,7590 h60
  text "Top Solder" at 10200.26,7590 h60
  text "Solder Resist" at 11130,7590 h60
  text "0.40mil" at 11989.77,7590 h60
  text "3.5" at 12639.6,7590 h60
  text "3" at 9790.34,7470 h60
  text "Top Layer" at 10200.26,7470 h60
  text "Copper" at 11130,7470 h60
  text "1.40mil" at 11989.77,7470 h60
  text "4" at 9790.34,7350 h60
  text "Dielectric1" at 10200.26,7350 h60
  text "FR-4" at 11130,7350 h60
  text "59.20mil" at 11989.77,7350 h60
  text "4.8" at 12639.6,7350 h60
  text "5" at 9790.34,7230 h60
  text "Bottom Layer" at 10200.26,7230 h60
  text "Copper" at 11130,7230 h60
  text "1.40mil" at 11989.77,7230 h60
  text "6" at 9790.34,7110 h60
  text "Bottom Solder" at 10200.26,7110 h60
  text "Solder Resist" at 11130,7110 h60
  text "0.40mil" at 11989.77,7110 h60
  text "3.5" at 12639.6,7110 h60
  text "7" at 9790.34,6990 h60
  text "Bottom Overlay" at 10200.26,6990 h60
  text ".Layer_Name" at 577,-858.49 h60
M13 Component Bodies Top:
  text ".Layer_Name" at 577,-858.49 h60
M14 Component Bodies Bottom:
  text ".Layer_Name" at 577,-858.49 h60
M15 Courtyards Top:
  text ".Layer_Name" at 577,-858.49 h60
M16 Courtyards Bottom:
  text ".Layer_Name" at 577,-858.49 h60
Drill Drawing:
  circle w10: c5363.8,2519.33 r27.66
  lines w10: 5336.14,2671.44 5391.46,2671.44 5363.8,2616.13 5336.14,2671.44 ; 5336.14,2754.41 5349.97,2754.41 5363.8,2740.59 5377.63,2754.41 5391.46,2754.41 5377.63,2768.24 5391.46,2782.07 5377.63,2782.07 5363.8,2795.9 5349.97,2782.07 5336.14,2782.07 5349.97,2768.24 5336.14,2754.41 ; 5336.14,2865.04 5391.46,2865.04 5391.46,2920.36 5336.14,2920.36 5336.14,2865.04 ; 5336.14,2989.5 5363.8,3003.33 5391.46,2989.5 5377.63,3017.16 5391.46,3044.82 5363.8,3030.99 5336.14,3044.82 5349.97,3017.16 5336.14,2989.5 ; 5336.14,3113.96 5391.46,3113.96 5391.46,3169.28 5336.14,3169.28 5336.14,3113.96 ; 5336.14,3238.42 5336.14,3252.25 5349.97,3266.08 5336.14,3279.91 5336.14,3293.74 5349.97,3293.74 5363.8,3279.91 5377.63,3293.74 5391.46,3293.74 5391.46,3279.91 5377.63,3266.08 5391.46,3252.25 5391.46,3238.42 5377.63,3238.42 5363.8,3252.25 5349.97,3238.42 5336.14,3238.42 ; 5347.21,3125.02 5380.39,3125.02 5380.39,3158.21 5347.21,3158.21 5347.21,3125.02
  lines w12: 5286,2454.33 8518.76,2454.33 ; 5286,3325.54 8518.76,3325.54 ; 5624.17,2329.87 5624.17,3450 ; 5956.28,2329.87 5956.28,3450 ; 6593.29,2329.87 6593.29,3450 ; 6852.64,2329.87 6852.64,3450 ; 7228.06,2329.87 7228.06,3450 ; 7951.91,2329.87 7951.91,3450 ; 5286,2329.87 8518.76,2329.87 8518.76,3450 5286,3450 5286,2329.87
  text "Symbol" at 5360.68,3362.88 h72
  text "Quantity" at 5661.51,3362.88 h72
  text "Finished Hole Size" at 5993.62,3362.88 h72
  text "Plated" at 6630.62,3362.88 h72
  text "Hole Type" at 6889.98,3362.88 h72
  text "Drill Layer Pair" at 7265.4,3362.88 h72
  text "Hole Tolerance" at 7989.25,3362.88 h72
  text "36" at 5661.51,3238.42 h60
  text "10.00mil (0.254mm)" at 5993.62,3238.42 h60
  text "PTH" at 6630.62,3238.42 h60
  text "Round" at 6889.98,3238.42 h60
  text "Top Layer - Bottom Layer" at 7265.4,3238.42 h60
  text "29" at 5661.51,3113.96 h60
  text "25.00mil (0.635mm)" at 5993.62,3113.96 h60
  text "PTH" at 6630.62,3113.96 h60
  text "Round" at 6889.98,3113.96 h60
  text "Top Layer - Bottom Layer" at 7265.4,3113.96 h60
  text "12" at 5661.51,2989.5 h60
  text "33.46mil (0.850mm)" at 5993.62,2989.5 h60
  text "PTH" at 6630.62,2989.5 h60
  text "Round" at 6889.98,2989.5 h60
  text "Top Layer - Bottom Layer" at 7265.4,2989.5 h60
  text "7" at 5661.51,2865.04 h60
  text "40.00mil (1.016mm)" at 5993.62,2865.04 h60
  text "PTH" at 6630.62,2865.04 h60
  text "Round" at 6889.98,2865.04 h60
  text "Top Layer - Bottom Layer" at 7265.4,2865.04 h60
  text "10" at 5661.51,2740.59 h60
  text "55.12mil (1.400mm)" at 5993.62,2740.59 h60
  text "PTH" at 6630.62,2740.59 h60
  text "Round" at 6889.98,2740.59 h60
  text "Top Layer - Bottom Layer" at 7265.4,2740.59 h60
  text "4" at 5661.51,2616.13 h60
  text "98.43mil (2.500mm)" at 5993.62,2616.13 h60
  text "PTH" at 6630.62,2616.13 h60
  text "Round" at 6889.98,2616.13 h60
  text "Top Layer - Bottom Layer" at 7265.4,2616.13 h60
  text "4" at 5661.51,2491.67 h60
  text "125.98mil (3.200mm)" at 5993.62,2491.67 h60
  text "PTH" at 6630.62,2491.67 h60
  text "Round" at 6889.98,2491.67 h60
  text "Top Layer - Bottom Layer" at 7265.4,2491.67 h60
  text "102 Total" at 5661.51,2367.21 h60
  text ".Layer_Name" at 577,-858.49 h60
M17 Embedded Cavity:
  text ".Layer_Name" at 577,-858.49 h60
M18 Embedded Assembly:
  text ".Layer_Name" at 577,-858.49 h60
M19 Embedded Keepout:
  text ".Layer_Name" at 577,-858.49 h60

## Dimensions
0,0 to 4000,0 on M2 Board Dimensions
0,0 to 0,2000 on M2 Board Dimensions
0,-400 to 1000,-400 on M2 Board Dimensions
